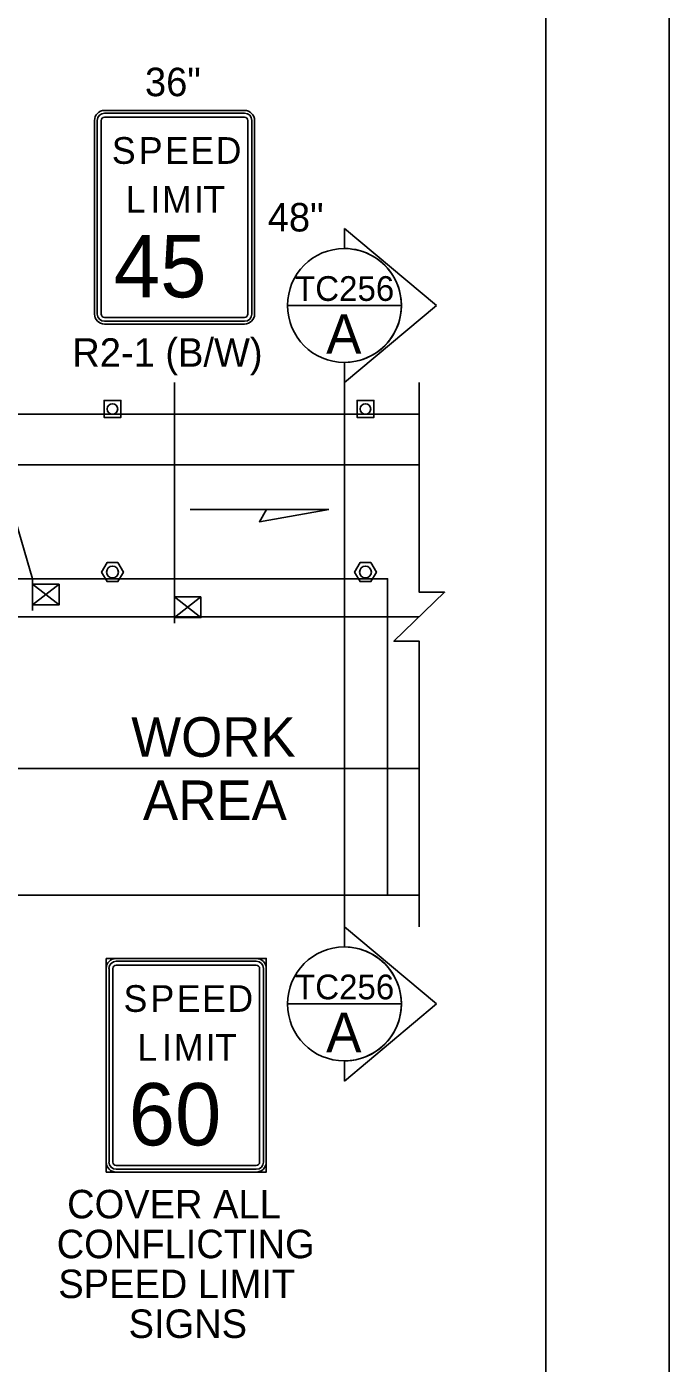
# Model space of a CAD drawing. Extents: x 99999 to 100116, y 99995 to 100013.
# Drawn here: x 100094.437 to 100096.062, y 100005.607 to 100008.987 of the extents above; entities that cross this region are included whole.
import ezdxf

# ---------------------------------------------------------------- set-up
doc = ezdxf.new("R2010")
doc.units = 0
for name, color, linetype in [('RD_MK_LineEdgeYellow', 7, 'Continuous'), ('RD_MK_LineLane', 7, 'Continuous'), ('SH_GI_PlotLimits', 7, 'Continuous'), ('SH_GI_SectionCut', 7, 'Continuous'), ('SH_GI_SheetBorder', 7, 'Continuous'), ('TR_SN_ConstructionSigns', 7, 'Continuous'), ('TR_WZ_PortableSignMount5ftMinBlk-Org', 7, 'Continuous'), ('TR_WZ_PortableSignMount5ftMinBlk-Wht', 7, 'Continuous'), ('TR_WZ_TallChanDevice', 7, 'Continuous'), ('TR_WZ_TrafficCone', 7, 'Continuous'), ('TR_WZ_WorkAreaLabel', 7, 'Continuous'), ('TR_WZ_WorkZoneDetails', 7, 'Continuous')]:
    doc.layers.add(name, color=color, linetype=linetype)

msp = doc.modelspace()

# ---------------------------------------------------------------- linework, layer by layer
at = {"layer": 'RD_MK_LineEdgeYellow'}
for p, q in [((100092.5055, 100007.8789), (100095.43, 100007.8789)), ((100088.195, 100007.1109), (100095.43, 100007.1109))]:
    msp.add_line(p, q, dxfattribs=at)
at = {"layer": 'RD_MK_LineLane'}
msp.add_lwpolyline([(100095.43, 100007.4949), (100088.195, 100007.4949)], dxfattribs=at)
at = {"layer": 'SH_GI_PlotLimits'}
msp.add_lwpolyline([(100079.0625, 99999.6875), (100096.0625, 99999.6875), (100096.0625, 100010.6875), (100079.0625, 100010.6875)], close=True, dxfattribs=at)
at = {"layer": 'SH_GI_SectionCut'}
for p, q in [((100095.2407, 100008.4258), (100095.2407, 100008.4767)), ((100095.2407, 100008.4767), (100095.4733, 100008.2818)), ((100095.4733, 100008.2818), (100095.2407, 100008.0869)), ((100095.2407, 100008.0869), (100095.2407, 100008.1378)), ((100095.2407, 100006.7109), (100095.2407, 100008.0869)), ((100095.2407, 100006.7109), (100095.2407, 100006.66)), ((100095.4733, 100006.516), (100095.2407, 100006.7109)), ((100095.2407, 100006.3211), (100095.4733, 100006.516)), ((100095.2407, 100006.372), (100095.2407, 100006.3211))]:
    msp.add_line(p, q, dxfattribs=at)
for points in [[(100095.0967, 100008.2818), (100095.3847, 100008.2818)], [(100095.0967, 100006.516), (100095.3847, 100006.516)]]:
    msp.add_lwpolyline(points, dxfattribs=at)
for centre in [(100095.2407, 100008.2818), (100095.2407, 100006.516)]:
    msp.add_circle(centre, 0.144, dxfattribs=at)
for centre in [(100095.2407, 100008.2818), (100095.2407, 100006.516)]:
    msp.add_arc(centre, 0.144, 269.9978, 90.0022, dxfattribs=at)
at = {"layer": 'SH_GI_SheetBorder'}
msp.add_line((100095.75, 100010.375), (100095.75, 100000), dxfattribs=at)
at = {"layer": 'TR_SN_ConstructionSigns'}
for p, q in [((100094.6337, 100008.7749), (100094.9881, 100008.7749)), ((100094.9881, 100008.7749), (100094.6337, 100008.7749)), ((100094.9881, 100008.7679), (100094.6337, 100008.7679)), ((100094.6337, 100008.758), (100094.9881, 100008.758)), ((100094.6084, 100008.2602), (100094.6084, 100008.7496)), ((100094.6084, 100008.7496), (100094.6084, 100008.2602)), ((100094.6154, 100008.7496), (100094.6154, 100008.2602)), ((100094.6253, 100008.2602), (100094.6253, 100008.7496)), ((100094.9965, 100008.7496), (100094.9965, 100008.2602)), ((100095.0064, 100008.2602), (100095.0064, 100008.7496)), ((100095.0134, 100008.7496), (100095.0134, 100008.2602)), ((100095.0134, 100008.2602), (100095.0134, 100008.7496)), ((100094.9881, 100008.2518), (100094.6337, 100008.2518)), ((100094.6337, 100008.2419), (100094.9881, 100008.2419)), ((100094.9881, 100008.2349), (100094.6337, 100008.2349)), ((100094.6337, 100008.2349), (100094.9881, 100008.2349)), ((100094.6633, 100006.6309), (100095.0177, 100006.6309)), ((100095.0177, 100006.6309), (100094.6633, 100006.6309)), ((100095.0177, 100006.6239), (100094.6633, 100006.6239)), ((100094.638, 100006.1162), (100094.638, 100006.6056)), ((100094.638, 100006.6056), (100094.638, 100006.1162)), ((100094.6451, 100006.6056), (100094.6451, 100006.1162)), ((100094.6549, 100006.1162), (100094.6549, 100006.6056)), ((100094.6633, 100006.614), (100095.0177, 100006.614)), ((100095.0261, 100006.6056), (100095.0261, 100006.1162)), ((100095.036, 100006.1162), (100095.036, 100006.6056)), ((100095.043, 100006.6056), (100095.043, 100006.1162)), ((100095.043, 100006.1162), (100095.043, 100006.6056)), ((100095.0177, 100006.1078), (100094.6633, 100006.1078)), ((100094.6633, 100006.0979), (100095.0177, 100006.0979)), ((100095.0177, 100006.0909), (100094.6633, 100006.0909)), ((100094.6633, 100006.0909), (100095.0177, 100006.0909))]:
    msp.add_line(p, q, dxfattribs=at)
msp.add_lwpolyline([(100094.638, 100006.6309), (100095.043, 100006.6309), (100095.043, 100006.0909), (100094.638, 100006.0909)], close=True, dxfattribs=at)
for centre, radius, start, end in [((100094.6337, 100008.7496), 0.0253, 90, 180), ((100094.6337, 100008.7496), 0.0253, 90, 180), ((100094.6337, 100008.7496), 0.0183, 90, 180), ((100094.6337, 100008.7496), 0.00844, 90, 180), ((100094.9881, 100008.7496), 0.0253, 360, 90), ((100094.9881, 100008.7496), 0.0253, 360, 90), ((100094.9881, 100008.7496), 0.0183, 0, 90), ((100094.9881, 100008.7496), 0.00844, 360, 90), ((100094.6337, 100008.2602), 0.0253, 180, 270), ((100094.6337, 100008.2602), 0.0253, 180, 270), ((100094.6337, 100008.2602), 0.0183, 180, 270), ((100094.6337, 100008.2602), 0.00844, 180, 270), ((100094.9881, 100008.2602), 0.0253, 270, 360), ((100094.9881, 100008.2602), 0.0183, 270, 360), ((100094.9881, 100008.2602), 0.00844, 270, 0), ((100094.9881, 100008.2602), 0.0253, 270, 360), ((100094.6633, 100006.6056), 0.0253, 90, 180), ((100094.6633, 100006.6056), 0.0253, 90, 180), ((100094.6633, 100006.6056), 0.0183, 90, 180), ((100095.0177, 100006.6056), 0.0253, 0, 90), ((100095.0177, 100006.6056), 0.0253, 360, 90), ((100095.0177, 100006.6056), 0.0183, 0, 90), ((100094.6633, 100006.6056), 0.00844, 90, 180), ((100095.0177, 100006.6056), 0.00844, 360, 90), ((100094.6633, 100006.1162), 0.0253, 180, 270), ((100094.6633, 100006.1162), 0.0253, 180, 270), ((100094.6633, 100006.1162), 0.0183, 180, 270), ((100094.6633, 100006.1162), 0.00844, 180, 270), ((100095.0177, 100006.1162), 0.0253, 270, 0), ((100095.0177, 100006.1162), 0.0183, 270, 360), ((100095.0177, 100006.1162), 0.00844, 270, 0), ((100095.0177, 100006.1162), 0.0253, 270, 0)]:
    msp.add_arc(centre, radius, start, end, dxfattribs=at)
at = {"layer": 'TR_WZ_PortableSignMount5ftMinBlk-Org'}
for p, q in [((100094.4519, 100007.5109), (100094.4519, 100007.5909)), ((100094.5186, 100007.5769), (100094.4519, 100007.5249)), ((100094.5186, 100007.5249), (100094.4519, 100007.5769)), ((100094.4853, 100007.5509), (100094.4853, 100007.5509)), ((100094.4854, 100007.551), (100094.4854, 100007.551))]:
    msp.add_line(p, q, dxfattribs=at)
for points in [[(100094.5186, 100007.5769), (100094.5186, 100007.5249), (100094.4519, 100007.5249), (100094.4519, 100007.5769)], [(100094.4519, 100007.5249), (100094.5186, 100007.5249), (100094.5186, 100007.5769), (100094.4519, 100007.5769)]]:
    msp.add_lwpolyline(points, close=True, dxfattribs=at)
at = {"layer": 'TR_WZ_PortableSignMount5ftMinBlk-Wht'}
for p, q in [((100094.8109, 100007.4789), (100094.8109, 100007.5589)), ((100094.8776, 100007.5449), (100094.8109, 100007.4929)), ((100094.8776, 100007.4929), (100094.8109, 100007.5449)), ((100094.8443, 100007.5189), (100094.8443, 100007.5189)), ((100094.8444, 100007.519), (100094.8444, 100007.519))]:
    msp.add_line(p, q, dxfattribs=at)
msp.add_lwpolyline([(100094.8776, 100007.5449), (100094.8776, 100007.4929), (100094.8109, 100007.4929), (100094.8109, 100007.5449)], close=True, dxfattribs=at)
at = {"layer": 'TR_WZ_TallChanDevice'}
for points in [[(100094.6678, 100007.6319), (100094.6401, 100007.6319), (100094.6262, 100007.6079), (100094.6401, 100007.5839), (100094.6678, 100007.5839), (100094.6816, 100007.6079)], [(100095.3078, 100007.6319), (100095.2801, 100007.6319), (100095.2662, 100007.6079), (100095.2801, 100007.5839), (100095.3078, 100007.5839), (100095.3216, 100007.6079)]]:
    msp.add_lwpolyline(points, close=True, dxfattribs=at)
for points in [[(100094.6678, 100007.6319), (100094.6401, 100007.6319), (100094.6262, 100007.6079), (100094.6401, 100007.5839), (100094.6678, 100007.5839), (100094.6816, 100007.6079), (100094.6678, 100007.6319)], [(100095.3078, 100007.6319), (100095.2801, 100007.6319), (100095.2662, 100007.6079), (100095.2801, 100007.5839), (100095.3078, 100007.5839), (100095.3216, 100007.6079), (100095.3078, 100007.6319)]]:
    msp.add_lwpolyline(points, dxfattribs=at)
for centre in [(100094.6539, 100007.6079), (100095.2939, 100007.6079)]:
    msp.add_circle(centre, 0.015, dxfattribs=at)
at = {"layer": 'TR_WZ_TrafficCone'}
for points in [[(100094.6326, 100007.9989), (100094.6753, 100007.9989), (100094.6753, 100008.0416), (100094.6326, 100008.0416), (100094.6326, 100007.9989)], [(100094.6326, 100008.0416), (100094.6753, 100008.0416), (100094.6753, 100007.9989), (100094.6326, 100007.9989), (100094.6326, 100008.0416)], [(100095.2726, 100007.9989), (100095.3153, 100007.9989), (100095.3153, 100008.0416), (100095.2726, 100008.0416), (100095.2726, 100007.9989)], [(100095.2726, 100008.0416), (100095.3153, 100008.0416), (100095.3153, 100007.9989), (100095.2726, 100007.9989), (100095.2726, 100008.0416)]]:
    msp.add_lwpolyline(points, dxfattribs=at)
for centre in [(100094.6539, 100008.0202), (100095.2939, 100008.0202)]:
    msp.add_circle(centre, 0.0133, dxfattribs=at)
at = {"layer": 'TR_WZ_WorkZoneDetails'}
for p, q in [((100094.4519, 100007.5909), (100094.1215, 100008.7148)), ((100094.8109, 100007.5589), (100094.8109, 100008.0869)), ((100092.5055, 100008.0069), (100095.43, 100008.0069)), ((100095.0436, 100007.7659), (100094.8508, 100007.7659)), ((100088.195, 100006.7909), (100095.43, 100006.7909))]:
    msp.add_line(p, q, dxfattribs=at)
msp.add_lwpolyline([(100095.43, 100006.7109), (100095.43, 100007.433), (100095.366, 100007.433), (100095.494, 100007.5569), (100095.43, 100007.5569), (100095.43, 100008.0869)], dxfattribs=at)
for points in [[(100095.2009, 100007.7659), (100095.0258, 100007.735), (100095.0436, 100007.7659)], [(100088.275, 100006.7909), (100088.275, 100007.5909), (100089.3339, 100007.5909), (100090.1739, 100007.4629), (100090.1739, 100007.4629), (100090.1739, 100007.4629), (100090.1739, 100007.4629), (100090.1739, 100007.4629), (100090.1739, 100007.4629), (100090.1739, 100007.4629), (100093.3739, 100007.4629), (100094.3814, 100007.5909), (100095.35, 100007.5909), (100095.35, 100007.2709), (100095.35, 100006.7909)]]:
    msp.add_lwpolyline(points, close=True, dxfattribs=at)

# ---------------------------------------------------------------- texts
at = {"layer": 'SH_GI_SectionCut'}
for p in [(100095.1158, 100008.2934), (100095.1158, 100006.5276)]:
    msp.add_text('TC256', height=0.0625, dxfattribs=at).set_placement(p)
for p in [(100095.1945, 100008.1598), (100095.1945, 100006.394)]:
    msp.add_text('A', height=0.1, rotation=359.99, dxfattribs=at).set_placement(p)
at = {"layer": 'TR_SN_ConstructionSigns'}
for s, height, p in [('36"', 0.072, (100094.7361, 100008.8109)), ('S', 0.0675, (100094.6523, 100008.6399)), ('P', 0.0675, (100094.7205, 100008.6399)), ('E', 0.0675, (100094.7866, 100008.6399)), ('E', 0.0675, (100094.8507, 100008.6399)), ('D', 0.0675, (100094.9149, 100008.6399)), ('L', 0.0675, (100094.6874, 100008.5162)), ('I', 0.0675, (100094.7495, 100008.5162)), ('M', 0.0675, (100094.7792, 100008.5162)), ('I', 0.0675, (100094.8602, 100008.5162)), ('T', 0.0675, (100094.8838, 100008.5162)), ('48"', 0.072, (100095.0467, 100008.4689)), ('R2-1 (B/W)', 0.072, (100094.5522, 100008.1269))]:
    msp.add_text(s, height=height, rotation=360, dxfattribs=at).set_placement(p)
for s, height, p in [('45', 0.1575, (100094.6574, 100008.3024)), ('S', 0.0675, (100094.6819, 100006.4959)), ('P', 0.0675, (100094.7501, 100006.4959)), ('E', 0.0675, (100094.8162, 100006.4959)), ('E', 0.0675, (100094.8803, 100006.4959)), ('D', 0.0675, (100094.9445, 100006.4959)), ('L', 0.0675, (100094.717, 100006.3722)), ('I', 0.0675, (100094.7791, 100006.3722)), ('M', 0.0675, (100094.8088, 100006.3722)), ('I', 0.0675, (100094.8898, 100006.3722)), ('T', 0.0675, (100094.9134, 100006.3722)), ('60', 0.1575, (100094.6949, 100006.1584)), ('COVER ALL', 0.072, (100094.5392, 100005.9739)), ('CONFLICTING', 0.072, (100094.5128, 100005.8731)), ('SPEED LIMIT', 0.072, (100094.5168, 100005.7723)), ('SIGNS', 0.072, (100094.6947, 100005.6715))]:
    msp.add_text(s, height=height, dxfattribs=at).set_placement(p)
at = {"layer": 'TR_WZ_WorkAreaLabel'}
for s, p in [('WORK', (100094.7013, 100007.1409)), ('AREA', (100094.7309, 100006.9809))]:
    msp.add_text(s, height=0.1, dxfattribs=at).set_placement(p)

doc.saveas('drawing.dxf')
